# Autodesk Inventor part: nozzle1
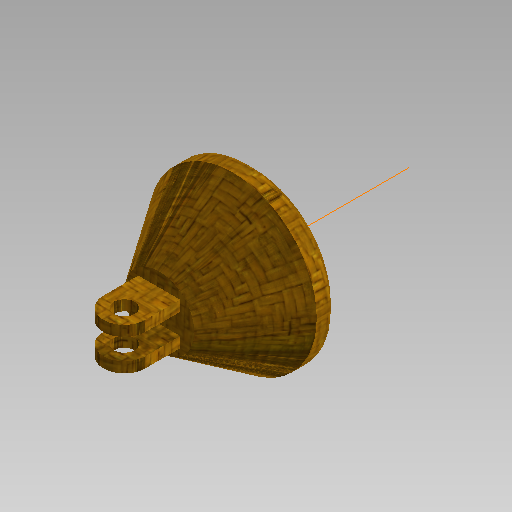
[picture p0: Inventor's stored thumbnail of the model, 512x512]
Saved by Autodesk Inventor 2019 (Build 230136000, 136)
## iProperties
Created: 2000-03
Part Number: nozzle1
User Status: Reference File
Document SubType Name: Modeling
Designer: Peter Roberts
Density: 1 g/cm^3
Material: Allgemein
Appearance: Blattgold (Oberfläche)
Manager: Dave Ford
Company: Autodesk Inc.
Control State: 0
Master: False
Checked Out: False
Shininess: 0.0
Length Units: 11269
Angle Units: 11279
Time Units: 11290
Mass Units: 11284
Length Display Precision: 1
Angle Display Precision: 2
Compacted: True
PropertySet Name: Model Information
Density: 0.0
Volumn: 0.0
Area: 0.0
Subject: Tutorial #3 part file
Author: Peter Roberts
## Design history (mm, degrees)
node "Volumenkörper1"
node "Volumenkörpern"
node "Oberflächenkörpern"
sketch "Sketch1"
  geometry: L1 (0, 0)-(0, 27); L2 (0, 27)-(-24, 27); L3 (-24, 27)-(-24, 21); L4 (0, 0)-(-10, 0); L5 (-10, 0)-(-24, 21); L6 (-6, 0)-(-6, -10); L7 (6, -10)-(6, 0); L8 (6, 0)-(-6, 0); A1 r 6 centre (0, -10) between (-6, -10) and (6, -10)
  constraints: 16 end point, 4 perpendicular, 2 parallel, 2 point on circle, 2 tangent, 1 centre point, 1 point on line, 1 vertical
  dimensions: "d0" = 27 distance of L1.start L1.end; "d1" = 24 distance of L1.end L2.end; "d2" = 6 distance of L2.end L3.end; "d3" = 10 distance of L1.start L4.end; "d5" = 10 distance of L7.start L7.end; "d6" = 6 radius of A1; "d7" = 6 distance between parallel lines of L6 L1
node "Revolution1" dims "d4" = 90 deg
node "Extrusion1" dims "d8" = 12, "d9" = 0
node "Extrusion2" dims "d10" = 6, "d11" = 0
node "Chamfer1" dims "d12" = 2, "d13" = 2, "d20" = 45 deg
node "Hole1" dims "d14" = 6, "d15" = 4, "d16" = 2, "d17" = 60 deg, "d18" = 8, "d19" = 118 deg
workaxis "Work Axis1"
sketch "Sketch2"
  geometry: A1 r 6 centre (0, -10) between (-6, -10) and (6, -10) reference; 1 further point
  constraints: 1 coincident
